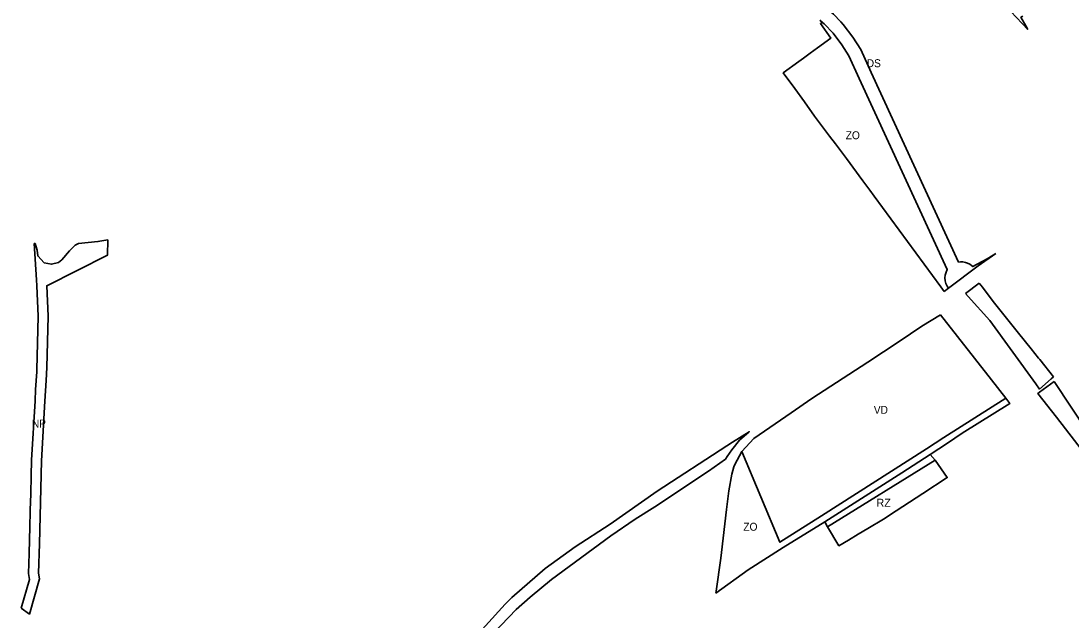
# Model space of a CAD drawing. Extents: x -650971 to -642489, y -1074311 to -1062745.
# Drawn here: x -649001 to -647426, y -1072500 to -1071601 of the extents above; entities that cross this region are included whole.
import ezdxf

# ---------------------------------------------------------------- set-up
doc = ezdxf.new("R2010")
doc.units = 0
doc.header["$LTSCALE"] = 4.8
for name, color, linetype, lineweight in [('15', 7, 'Continuous', 35), ('24', 7, 'Continuous', 35), ('35', 7, 'Continuous', 35), ('42', 7, 'Continuous', 35), ('48', 7, 'Continuous', 35), ('6', 7, 'Continuous', 35), ('62', 7, 'Continuous', 35)]:
    doc.layers.add(name, color=color, linetype=linetype, lineweight=lineweight)

msp = doc.modelspace()

# ---------------------------------------------------------------- linework, layer by layer
at = {"layer": '15'}
for points in [[(-647490.561, -1071613.609), (-647516.376, -1071586.89), (-647568.35, -1071496.656), (-647576.471, -1071481.091)], [(-647498.271, -1071593.544), (-647501.11, -1071595.45), (-647493.6, -1071608.5), (-647490.561, -1071613.609)]]:
    msp.add_lwpolyline(points, dxfattribs=at)
msp.add_lwpolyline([(-647795.4, -1072352.415), (-647679.66, -1072279.15), (-647637.082, -1072251.377), (-647629.67, -1072259.82), (-647791.198, -1072360.119)], close=True, dxfattribs=at)
at = {"layer": '24'}
msp.add_line((-647584.202, -1072009.747), (-647563.77, -1071994.38), dxfattribs=at)
for points in [[(-647786.379, -1071587.401), (-647782.408, -1071590.847), (-647771.408, -1071602.414)], [(-647609.808, -1072001.962), (-647611.779, -1071999.069), (-647613.637, -1071995.081), (-647614.76, -1071990.762), (-647615.083, -1071986.65), (-647614.654, -1071982.238), (-647613.455, -1071978.031), (-647611.514, -1071974.086), (-647743.48, -1071687.426), (-647758.994, -1071653.513), (-647769.498, -1071636.647), (-647782.97, -1071619.278), (-647796.24, -1071605.324), (-647798.8, -1071603.102), (-647802.849, -1071599.589)], [(-647771.408, -1071602.414), (-647767.784, -1071606.225), (-647753.065, -1071625.201), (-647741.34, -1071644.028), (-647725.672, -1071678.279), (-647594.731, -1071962.714), (-647591.518, -1071962.387), (-647588.064, -1071962.51), (-647584.363, -1071963.196), (-647581.036, -1071964.346), (-647577.881, -1071965.979), (-647575.415, -1071967.709), (-647573.283, -1071969.627), (-647551.962, -1071958.049), (-647538.882, -1071950.07)], [(-647538.882, -1071950.07), (-647565.32, -1071968.57), (-647609.808, -1072001.962)], [(-647563.77, -1071994.38), (-647558.97, -1072000.62), (-647542.57, -1072021.99)], [(-647478.73, -1072145.53), (-647547.919, -1072050.435), (-647580.065, -1072014.386), (-647584.202, -1072009.747)], [(-647542.57, -1072021.99), (-647504.73, -1072069.29), (-647485.6, -1072093.2), (-647474.72, -1072106.81), (-647472.86, -1072109.13), (-647452.23, -1072134.91)], [(-647452.23, -1072134.91), (-647455.83, -1072137.96), (-647473.022, -1072153.375), (-647478.73, -1072145.53)], [(-647376.68, -1072222.29), (-647392.34, -1072250.02), (-647396.25, -1072252.14), (-647404.45, -1072250.66), (-647407.34, -1072247.93), (-647447.73, -1072195.72), (-647475.57, -1072159.74), (-647473.12, -1072157.91), (-647451.21, -1072142.08)], [(-647451.21, -1072142.08), (-647401.221, -1072217.342), (-647376.68, -1072222.29)], [(-648303.791, -1072531.792), (-648258.165, -1072484.283), (-648237.406, -1072465.811), (-648205.298, -1072439.308), (-648116.32, -1072373.44), (-648079.76, -1072348.46), (-648050.276, -1072330.025), (-647969.894, -1072276.479), (-647944.45, -1072258.458), (-647941.77, -1072254.45), (-647934.9, -1072244.55), (-647923.16, -1072229.85), (-647908.5, -1072217.29), (-647933.95, -1072233.18), (-647942.21, -1072238.54), (-648046.69, -1072306.3), (-648117.12, -1072356), (-648169.81, -1072390.035), (-648214.73, -1072422.41), (-648264.618, -1072466.244), (-648274.53, -1072476.196), (-648328.847, -1072535.816)]]:
    msp.add_lwpolyline(points, dxfattribs=at)
at = {"layer": '35'}
for points in [[(-647919.68, -1072247.09), (-647901.91, -1072227.6), (-647845.58, -1072188.94), (-647814.58, -1072167.67), (-647730.53, -1072112.84), (-647683.63, -1072081.94), (-647649.76, -1072059.06), (-647621.97, -1072041.73)], [(-647621.97, -1072041.73), (-647545.44, -1072139.35), (-647523.71, -1072167.071)], [(-647523.71, -1072167.071), (-647616.719, -1072226.154), (-647642.504, -1072242.974), (-647800.2, -1072343.615), (-647862.615, -1072383.084), (-647919.68, -1072247.09)]]:
    msp.add_lwpolyline(points, dxfattribs=at)
at = {"layer": '42'}
for points in [[(-647817.33, -1071649.51), (-647806.35, -1071641.47), (-647786.1, -1071626.65), (-647801.84, -1071604.97), (-647798.8, -1071603.102)], [(-647798.8, -1071603.102), (-647796.24, -1071605.324), (-647782.97, -1071619.278), (-647769.498, -1071636.647), (-647758.994, -1071653.513), (-647743.48, -1071687.426), (-647611.514, -1071974.086), (-647613.455, -1071978.031), (-647614.654, -1071982.238), (-647615.083, -1071986.65), (-647614.76, -1071990.762), (-647613.637, -1071995.081), (-647611.779, -1071999.069), (-647609.808, -1072001.962), (-647616.12, -1072006.7)], [(-647616.12, -1072006.7), (-647621.06, -1072000), (-647721.3, -1071863.74), (-647727.85, -1071854.86), (-647738.21, -1071840.78), (-647762.69, -1071807.58), (-647779.22, -1071785.33), (-647788.08, -1071773.61), (-647810.72, -1071743.62), (-647825.58, -1071722.28), (-647840.32, -1071702.31), (-647857.52, -1071678.92), (-647834.345, -1071661.969), (-647827.42, -1071656.89), (-647817.33, -1071649.51)], [(-647919.68, -1072247.09), (-647862.615, -1072383.084), (-647800.2, -1072343.615), (-647642.504, -1072242.974), (-647616.719, -1072226.154), (-647523.71, -1072167.071)], [(-647523.71, -1072167.071), (-647517.51, -1072174.98), (-647589.02, -1072219.66), (-647611.306, -1072234.563), (-647637.082, -1072251.377)], [(-647958.82, -1072459.74), (-647958.18, -1072456.36), (-647951.21, -1072407.13), (-647950.2, -1072398.61), (-647942.54, -1072333.82), (-647939.26, -1072306.1), (-647934.86, -1072280.99), (-647931.51, -1072270.11), (-647930.36, -1072266.38), (-647919.68, -1072247.09)], [(-647637.082, -1072251.377), (-647679.66, -1072279.15), (-647795.4, -1072352.415)], [(-647795.4, -1072352.415), (-647857.52, -1072391.14), (-647910.27, -1072424.51), (-647958.82, -1072459.74)]]:
    msp.add_lwpolyline(points, dxfattribs=at)
at = {"layer": '48'}
msp.add_line((-649000.851, -1072482.138), (-648988.27, -1072439.04), dxfattribs=at)
for points in [[(-648870.458, -1071929.441), (-648871.27, -1071952.643), (-648962.195, -1071998.309), (-648960.263, -1072043.893), (-648962.165, -1072120.949), (-648963.052, -1072140.301), (-648964.865, -1072171.684), (-648970.001, -1072260.788), (-648973.274, -1072385.724), (-648974.424, -1072429.462), (-648973.238, -1072438.27), (-648988.248, -1072491.089), (-649000.851, -1072482.138)], [(-648980.94, -1071935.12), (-648979.85, -1071935.11), (-648976.85, -1071944.78), (-648975.65, -1071953.47), (-648966.01, -1071963.74), (-648955.25, -1071966.15), (-648944.69, -1071963.44), (-648939.51, -1071959.25), (-648928.11, -1071946.04), (-648925.64, -1071943.18), (-648919.79, -1071937.27), (-648914.45, -1071934.78), (-648885.56, -1071932.1), (-648870.458, -1071929.441)], [(-648988.27, -1072439.04), (-648989.45, -1072430.27), (-648988.65, -1072399.86), (-648987.6, -1072359.77), (-648987.02, -1072337.8), (-648986.95, -1072334.96), (-648986.31, -1072310.66), (-648985.6, -1072283.43), (-648984.99, -1072260.16), (-648979.84, -1072170.82), (-648978.87, -1072154.04), (-648977.33, -1072127.34), (-648977.3, -1072126.08), (-648977.26, -1072124.65), (-648975.27, -1072044.01), (-648976.91, -1071998.2), (-648977.48, -1071989.2), (-648980.94, -1071935.12)]]:
    msp.add_lwpolyline(points, dxfattribs=at)
at = {"layer": '6'}
msp.add_line((-647791.198, -1072360.119), (-647629.67, -1072259.82), dxfattribs=at)
msp.add_lwpolyline([(-647629.67, -1072259.82), (-647611.51, -1072286.26), (-647648.09, -1072309.95), (-647688.26, -1072336.06), (-647707.33, -1072348.35), (-647730.97, -1072362.6), (-647745.32, -1072371.26), (-647759.68, -1072379.91), (-647774.04, -1072388.57), (-647791.198, -1072360.119)], dxfattribs=at)

# ---------------------------------------------------------------- texts
at = {"layer": '62', "width": 0.95}
for s, p in [('DS', (-647732.378, -1071670.379)), ('ZO', (-647763.886, -1071778.486)), ('VD', (-647721.74, -1072190.495)), ('NP', (-648984.583, -1072211.041)), ('ZO', (-647917.457, -1072365.915))]:
    msp.add_text(s, height=12, dxfattribs=at).set_placement(p)
at = {"layer": '62'}
msp.add_text('RZ', height=12, dxfattribs=at).set_placement((-647717.713, -1072329.92))

doc.saveas('drawing.dxf')
